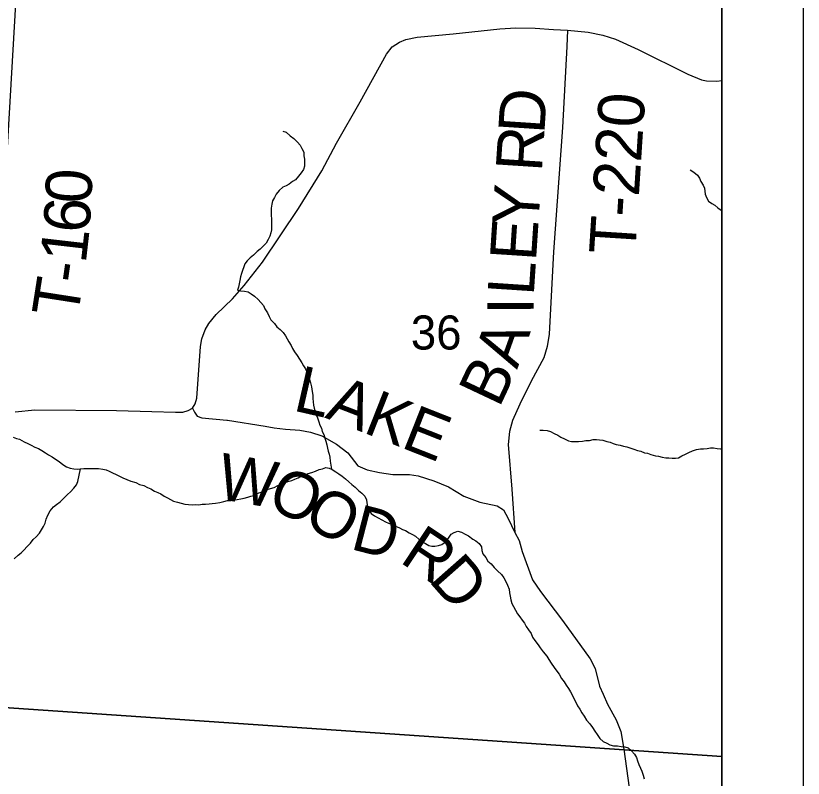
# Model space of a CAD drawing. Extents: x -20.2 to 34, y 0 to 22.
# Drawn here: x 8.033 to 9, y 17.818 to 18.755 of the extents above; entities that cross this region are included whole.
import ezdxf

# ---------------------------------------------------------------- set-up
doc = ezdxf.new("R2010")
doc.units = 0
for name, color, linetype in [('Default', 7, 'Continuous'), ('GM_X_County_Road', 7, 'Continuous'), ('GM_X_Minor_River', 7, 'Continuous'), ('GM_X_Section_Text', 7, 'Continuous'), ('GM_X_Township_Road', 7, 'Continuous'), ('GM_X_Township_Road_Text', 7, 'Continuous'), ('SH_Cut_Line', 7, 'Continuous'), ('SH_Data', 7, 'Continuous')]:
    doc.layers.add(name, color=color, linetype=linetype)

msp = doc.modelspace()

# ---------------------------------------------------------------- linework, layer by layer
at = {"layer": 'Default'}
msp.add_lwpolyline([(8.9, 14.81759), (8.9, 20.9), (8.15084, 20.9), (8.1316, 20.55479), (8.07091, 19.45221), (8.04849, 19.09144), (8.043, 18.90974), (7.80715, 18.91995), (7.53952, 18.93824), (7.38712, 18.94649), (6.53318, 18.99275), (5.90057, 19.02599), (5.87099, 18.53836), (5.80691, 17.48436), (5.78313, 17.24828), (5.78116, 17.15273), (5.73681, 16.42062)], dxfattribs=at)
for points in [[(8.9, 17.84514), (8.9, 18.87213), (8.04045, 18.91171), (7.98194, 17.90766)], [(8.9, 16.85373), (8.9, 17.84514), (7.98194, 17.90766), (7.92004, 16.89751)]]:
    msp.add_lwpolyline(points, close=True, dxfattribs=at)
at = {"layer": 'GM_X_County_Road'}
msp.add_lwpolyline([(8.03173, 18.26848), (8.05577, 18.27117), (8.15635, 18.27014), (8.19983, 18.26904), (8.2289, 18.2682), (8.23777, 18.2682), (8.24413, 18.27014), (8.24948, 18.27305), (8.25298, 18.27859), (8.25494, 18.28537), (8.25964, 18.34879), (8.26131, 18.3582), (8.26519, 18.36928), (8.26989, 18.37704), (8.27875, 18.38812), (8.29869, 18.4075), (8.31309, 18.42384), (8.33553, 18.45236), (8.37969, 18.51827), (8.40836, 18.56452), (8.42663, 18.59858), (8.45571, 18.64953), (8.48805, 18.70792), (8.49476, 18.71683), (8.5039, 18.72264), (8.51193, 18.72624), (8.52578, 18.72901), (8.57008, 18.73293), (8.62713, 18.73926), (8.64679, 18.74036), (8.67061, 18.74009), (8.69304, 18.73815), (8.71028, 18.73733), (8.73569, 18.73511), (8.75369, 18.7315), (8.76919, 18.72652), (8.79717, 18.71378), (8.85809, 18.6836), (8.87498, 18.67639), (8.88103, 18.6751), (8.89381, 18.67474), (8.9, 18.67559)], dxfattribs=at)
at = {"layer": 'GM_X_Minor_River'}
for points in [[(8.36074, 18.61331), (8.36493, 18.61222), (8.36954, 18.60771), (8.37414, 18.60435), (8.37874, 18.59985), (8.38182, 18.59609), (8.38415, 18.59232), (8.38648, 18.58779), (8.38653, 18.58323), (8.38734, 18.57906), (8.38739, 18.57488), (8.38707, 18.57032), (8.38597, 18.5665), (8.38336, 18.56229), (8.38, 18.55807), (8.37625, 18.55384), (8.37248, 18.55151), (8.36834, 18.54842), (8.36457, 18.54647), (8.3608, 18.54453), (8.35629, 18.54067), (8.35255, 18.53606), (8.35032, 18.53186), (8.34809, 18.52803), (8.347, 18.52383), (8.3463, 18.51889), (8.34635, 18.51471), (8.3464, 18.51015), (8.34684, 18.50521), (8.34688, 18.50141), (8.34656, 18.49685), (8.34661, 18.49229), (8.3459, 18.48848), (8.34481, 18.48429), (8.34257, 18.48046), (8.33997, 18.47587), (8.3366, 18.47203), (8.33285, 18.46856), (8.32909, 18.46547), (8.32458, 18.46123), (8.32045, 18.45776), (8.31669, 18.4543), (8.31408, 18.45046), (8.31261, 18.44664), (8.31114, 18.44245), (8.30966, 18.43863), (8.30857, 18.43444), (8.30787, 18.42987), (8.30715, 18.42606), (8.30607, 18.42186), (8.30497, 18.41805), (8.30878, 18.41734), (8.31334, 18.41702), (8.3179, 18.41593), (8.32173, 18.4137), (8.32594, 18.41071), (8.33016, 18.40659), (8.33362, 18.40283), (8.3367, 18.39907), (8.33864, 18.39529), (8.34174, 18.39039), (8.34369, 18.38586), (8.34602, 18.38171), (8.35025, 18.3772), (8.35333, 18.37306), (8.35755, 18.36969), (8.36101, 18.36594), (8.36371, 18.36217), (8.36603, 18.3584), (8.36797, 18.35463), (8.37068, 18.3501), (8.37263, 18.34632), (8.37495, 18.34217), (8.37842, 18.33766), (8.38113, 18.33313), (8.38384, 18.32899), (8.38616, 18.32521), (8.38848, 18.32144), (8.39043, 18.31691), (8.392, 18.31275), (8.3932, 18.30821), (8.39476, 18.30404), (8.39596, 18.2995), (8.39679, 18.29343), (8.39759, 18.28926), (8.39764, 18.28508), (8.39807, 18.28091), (8.3985, 18.27673), (8.3993, 18.27294), (8.40049, 18.26916), (8.40167, 18.26499), (8.40324, 18.26121), (8.40482, 18.25629), (8.406, 18.25213), (8.40795, 18.24835), (8.40913, 18.24457), (8.41107, 18.24079), (8.41226, 18.23625), (8.41345, 18.23246), (8.41464, 18.22792), (8.41544, 18.22413)], [(8.86122, 18.566), (8.86543, 18.56302), (8.87003, 18.55928), (8.87235, 18.5555), (8.8743, 18.55173), (8.87701, 18.5472), (8.87857, 18.54342), (8.87899, 18.53963), (8.87942, 18.53583), (8.88098, 18.53205), (8.88369, 18.52753), (8.88752, 18.52454), (8.89134, 18.52268), (8.89517, 18.51931), (8.89901, 18.51632), (8.9, 18.5157)], [(8.02924, 18.23752), (8.03343, 18.23605), (8.03724, 18.23496), (8.04298, 18.23161), (8.04717, 18.22976), (8.05138, 18.22754), (8.05596, 18.22531), (8.06053, 18.22347), (8.06474, 18.22124), (8.06895, 18.21826), (8.07277, 18.21564), (8.07735, 18.21342), (8.08118, 18.21043), (8.08578, 18.20745), (8.09037, 18.20371), (8.09496, 18.2011), (8.09954, 18.19926), (8.10372, 18.19855), (8.1079, 18.19823), (8.11169, 18.19865), (8.11624, 18.19909), (8.12042, 18.19914), (8.12459, 18.1992)], [(8.67634, 18.24602), (8.68052, 18.24608), (8.68546, 18.24576), (8.68965, 18.24429), (8.69385, 18.24206), (8.69843, 18.23984), (8.70225, 18.23761), (8.70683, 18.23539), (8.71141, 18.23316), (8.71522, 18.23207), (8.7194, 18.23212), (8.72395, 18.23218), (8.72888, 18.23262), (8.73305, 18.23343), (8.73722, 18.23349), (8.74176, 18.23468), (8.74594, 18.23474), (8.74974, 18.2344), (8.75392, 18.2337), (8.75849, 18.23223), (8.76268, 18.23115), (8.7665, 18.22968), (8.77031, 18.22858), (8.77487, 18.2275), (8.77906, 18.22641), (8.78324, 18.22571), (8.78706, 18.22423), (8.79201, 18.22278), (8.7962, 18.22131), (8.80039, 18.22022), (8.80497, 18.21838), (8.80877, 18.21767), (8.81258, 18.2162), (8.81829, 18.21475), (8.8221, 18.21404), (8.82667, 18.21295), (8.83123, 18.21225), (8.83503, 18.2123), (8.83883, 18.21158), (8.843, 18.21164), (8.8468, 18.21207), (8.85094, 18.2144), (8.85547, 18.21673), (8.85962, 18.21868), (8.86378, 18.22064), (8.86869, 18.22222), (8.87362, 18.22304), (8.87741, 18.22309), (8.88196, 18.22352), (8.88613, 18.22434), (8.88992, 18.22438), (8.89411, 18.22368), (8.89829, 18.22297), (8.9, 18.22299)], [(8.41544, 18.22413), (8.41625, 18.22034), (8.41743, 18.21656), (8.41823, 18.21276), (8.41867, 18.20821), (8.42053, 18.19805)], [(8.03062, 18.0882), (8.03551, 18.09244), (8.03927, 18.09553), (8.04302, 18.099), (8.04601, 18.10284), (8.05052, 18.10707), (8.05388, 18.11168), (8.05764, 18.11514), (8.06176, 18.11975), (8.06399, 18.12358), (8.0666, 18.12779), (8.06845, 18.132), (8.06991, 18.13695), (8.07175, 18.14154), (8.07472, 18.14689), (8.07884, 18.15189), (8.0826, 18.15459), (8.08712, 18.15807), (8.09124, 18.1623), (8.09612, 18.16692), (8.09988, 18.17039), (8.104, 18.175), (8.10699, 18.17884), (8.10884, 18.18304), (8.11194, 18.19868)], [(8.12459, 18.1992), (8.12991, 18.19888), (8.13408, 18.19894), (8.13941, 18.19824), (8.14359, 18.19754), (8.14741, 18.19568), (8.15123, 18.19383), (8.15581, 18.19161), (8.16001, 18.18938), (8.16421, 18.18754), (8.16879, 18.18531), (8.17374, 18.18347), (8.18022, 18.18166), (8.18442, 18.17943), (8.18975, 18.17798), (8.19433, 18.17575), (8.19853, 18.17391), (8.20312, 18.17131), (8.20693, 18.16945), (8.21075, 18.16798), (8.21496, 18.165), (8.21878, 18.16314), (8.2226, 18.16091), (8.22642, 18.15906), (8.23137, 18.1576), (8.23556, 18.15651), (8.24013, 18.15505), (8.24469, 18.15473), (8.24963, 18.15441), (8.25342, 18.15484), (8.2576, 18.15451), (8.26138, 18.15532), (8.26556, 18.15537), (8.27011, 18.15543), (8.2739, 18.15586), (8.27807, 18.15629), (8.28338, 18.15711), (8.2883, 18.15832), (8.29246, 18.15951), (8.29664, 18.15956), (8.30042, 18.16037), (8.30459, 18.1608), (8.30914, 18.16162), (8.3133, 18.16243), (8.31746, 18.16362), (8.32124, 18.16519), (8.32541, 18.166), (8.33106, 18.16911), (8.3356, 18.17031), (8.34127, 18.17304), (8.34542, 18.17461), (8.34996, 18.17581), (8.35449, 18.17815), (8.35941, 18.17973), (8.36318, 18.1813), (8.36696, 18.18286), (8.3715, 18.18444), (8.37528, 18.18601), (8.37943, 18.18758), (8.38358, 18.18991), (8.38813, 18.19073), (8.3919, 18.19306), (8.39606, 18.19425), (8.40097, 18.19583), (8.40513, 18.19778), (8.40929, 18.19859), (8.41345, 18.20017), (8.41763, 18.19946), (8.42145, 18.19761), (8.42566, 18.195), (8.42948, 18.19239), (8.43369, 18.1894), (8.43753, 18.18641), (8.44174, 18.18266), (8.44558, 18.17929), (8.44942, 18.17592), (8.45364, 18.17217), (8.45785, 18.16881), (8.46131, 18.16505), (8.46326, 18.16051), (8.46369, 18.15672), (8.4645, 18.15217), (8.46606, 18.14839), (8.46915, 18.14387), (8.47336, 18.14088), (8.47757, 18.13828), (8.48215, 18.13605), (8.48674, 18.13345), (8.49055, 18.13198), (8.49513, 18.13014), (8.49894, 18.12829), (8.5039, 18.12607), (8.50772, 18.12421), (8.51153, 18.12274), (8.51574, 18.11976), (8.51994, 18.11791), (8.52377, 18.11568), (8.52799, 18.11193), (8.53182, 18.10894), (8.53602, 18.10671), (8.53984, 18.10448)], [(8.53984, 18.10448), (8.54364, 18.10377), (8.54744, 18.10344), (8.55199, 18.10425), (8.55615, 18.10582), (8.55991, 18.10853), (8.56403, 18.11352), (8.56739, 18.11812), (8.57116, 18.12045), (8.57569, 18.12203), (8.58026, 18.12095), (8.58447, 18.11834), (8.58867, 18.11611), (8.59403, 18.11238), (8.59785, 18.11015), (8.60169, 18.10678), (8.60477, 18.10264), (8.60521, 18.09808), (8.60639, 18.0943), (8.60986, 18.08978), (8.61257, 18.08525), (8.61678, 18.08189), (8.62025, 18.07737), (8.62448, 18.07325), (8.62908, 18.06875), (8.63217, 18.0646), (8.6345, 18.06007), (8.63683, 18.05554), (8.63879, 18.05063), (8.63922, 18.04645), (8.64002, 18.04228), (8.64084, 18.03774), (8.64203, 18.03319), (8.64397, 18.02942), (8.64668, 18.02489), (8.64901, 18.02036), (8.65171, 18.01659), (8.6548, 18.01283), (8.6575, 18.00907), (8.65944, 18.00491), (8.66253, 18.00077), (8.66562, 17.99625), (8.66757, 17.99172), (8.67028, 17.98757), (8.67451, 17.9823), (8.67684, 17.97853), (8.68031, 17.97364), (8.68493, 17.96838), (8.68763, 17.96423), (8.69034, 17.95971), (8.69382, 17.95443), (8.69729, 17.94991), (8.69999, 17.94615), (8.70309, 17.94087), (8.70617, 17.93711), (8.70888, 17.93296), (8.71158, 17.92882), (8.71391, 17.92466), (8.71623, 17.92089), (8.7178, 17.91711), (8.7209, 17.91107), (8.72285, 17.9073), (8.72555, 17.90315), (8.72788, 17.899), (8.73096, 17.89486), (8.73368, 17.88996), (8.73791, 17.88545), (8.74099, 17.88093), (8.74409, 17.87641), (8.74679, 17.87226), (8.75027, 17.86737), (8.75411, 17.86362), (8.75869, 17.86139), (8.7625, 17.85954), (8.76669, 17.85846), (8.77163, 17.85814), (8.7762, 17.85743), (8.78075, 17.85711), (8.78495, 17.85564), (8.78916, 17.85228), (8.79263, 17.84814), (8.79495, 17.84399), (8.79652, 17.83983), (8.79809, 17.83529), (8.80004, 17.83076), (8.8016, 17.82698), (8.80318, 17.82244), (8.80475, 17.8179)]]:
    msp.add_lwpolyline(points, dxfattribs=at)
at = {"layer": 'GM_X_Township_Road'}
for points in [[(8.71028, 18.73733), (8.70965, 18.71738), (8.70412, 18.61797), (8.69304, 18.4651), (8.68766, 18.36404), (8.68528, 18.34907), (8.68113, 18.33495), (8.66562, 18.30614), (8.65176, 18.2779), (8.64292, 18.25796), (8.63904, 18.24439), (8.63737, 18.2286), (8.64208, 18.17349), (8.64548, 18.12017)], [(8.24948, 18.27305), (8.25194, 18.26832), (8.25531, 18.26328), (8.26131, 18.26111), (8.29181, 18.25855)], [(8.29181, 18.25855), (8.29276, 18.25847), (8.33874, 18.25105), (8.35015, 18.24887), (8.36384, 18.24743), (8.38136, 18.24599), (8.39481, 18.24359), (8.40849, 18.23902), (8.42674, 18.22894), (8.44043, 18.21813), (8.45267, 18.20229), (8.4642, 18.19749), (8.47932, 18.19412), (8.49565, 18.19148), (8.51606, 18.19148), (8.52686, 18.18981), (8.54631, 18.18404), (8.56432, 18.17636), (8.58281, 18.16483), (8.60274, 18.15763), (8.62387, 18.15306), (8.63155, 18.14802), (8.63731, 18.1377), (8.64548, 18.12017), (8.651, 18.11057), (8.6522, 18.10601)], [(8.6522, 18.10601), (8.65461, 18.09688), (8.66733, 18.06231), (8.67717, 18.0479), (8.70407, 18.01237), (8.7384, 17.9653), (8.74416, 17.9533), (8.74969, 17.93169), (8.75401, 17.9216), (8.75953, 17.9096), (8.77009, 17.89039), (8.77585, 17.87575), (8.7797, 17.85409), (8.78594, 17.80659)]]:
    msp.add_lwpolyline(points, dxfattribs=at)
at = {"layer": 'SH_Cut_Line'}
msp.add_lwpolyline([(5.77351, 14.1), (8.9, 14.1), (8.9, 20.9), (2.1, 20.9), (2.1, 14.1), (5.39535, 14.1), (5.72679, 14.10759)], close=True, dxfattribs=at)
at = {"layer": 'SH_Data'}
for p, q in [((9, 21), (9, 14)), ((8.9, 20.9), (8.9, 14.1))]:
    msp.add_line(p, q, dxfattribs=at)

# ---------------------------------------------------------------- texts
at = {"layer": 'GM_X_Section_Text'}
msp.add_text('36', height=0.041856, rotation=0.00001, dxfattribs=at).set_placement((8.51791, 18.34515))
at = {"layer": 'GM_X_Township_Road_Text'}
for s, height, rotation, p in [('D', 0.05682, 86.2599, (8.68182, 18.60923)), ('T-220', 0.056818, 86.3617, (8.79343, 18.46073)), ('R', 0.05682, 86.25988, (8.67878, 18.56267)), ('0', 0.05682, 87.49371, (8.12517, 18.5239)), ('Y', 0.05682, 86.25982, (8.67437, 18.4953)), ('6', 0.05682, 86.08371, (8.12269, 18.48746)), ('E', 0.05682, 86.26067, (8.6716, 18.45289)), ('1', 0.05682, 83.42461, (8.11842, 18.44983)), ('-', 0.05682, 81.8718, (8.1149, 18.42506)), ('L', 0.05682, 86.25604, (8.66882, 18.41048)), ('T', 0.05682, 81.14924, (8.10825, 18.3823)), ('I', 0.05682, 90.09239, (8.66889, 18.38815)), ('A', 0.05682, 70.29408, (8.6484, 18.32005)), ('B', 0.05682, 64.75462, (8.6262, 18.2723)), ('L', 0.05682, 347.16439, (8.37188, 18.27052)), ('A', 0.05682, 338.91228, (8.41125, 18.26171)), ('K', 0.05682, 338.43941, (8.45778, 18.24376)), ('E', 0.05682, 338.44501, (8.50429, 18.22538)), ('W', 0.05682, 350.14379, (8.27768, 18.16238)), ('O', 0.05682, 335.74568, (8.33894, 18.15222)), ('O', 0.05682, 329.52855, (8.38308, 18.13243)), ('D', 0.05682, 345.51759, (8.44212, 18.10047)), ('R', 0.05682, 326.39004, (8.50269, 18.08481)), ('D', 0.05682, 311.40182, (8.5386, 18.06155))]:
    msp.add_text(s, height=height, rotation=rotation, dxfattribs=at).set_placement(p)

doc.saveas('drawing.dxf')
